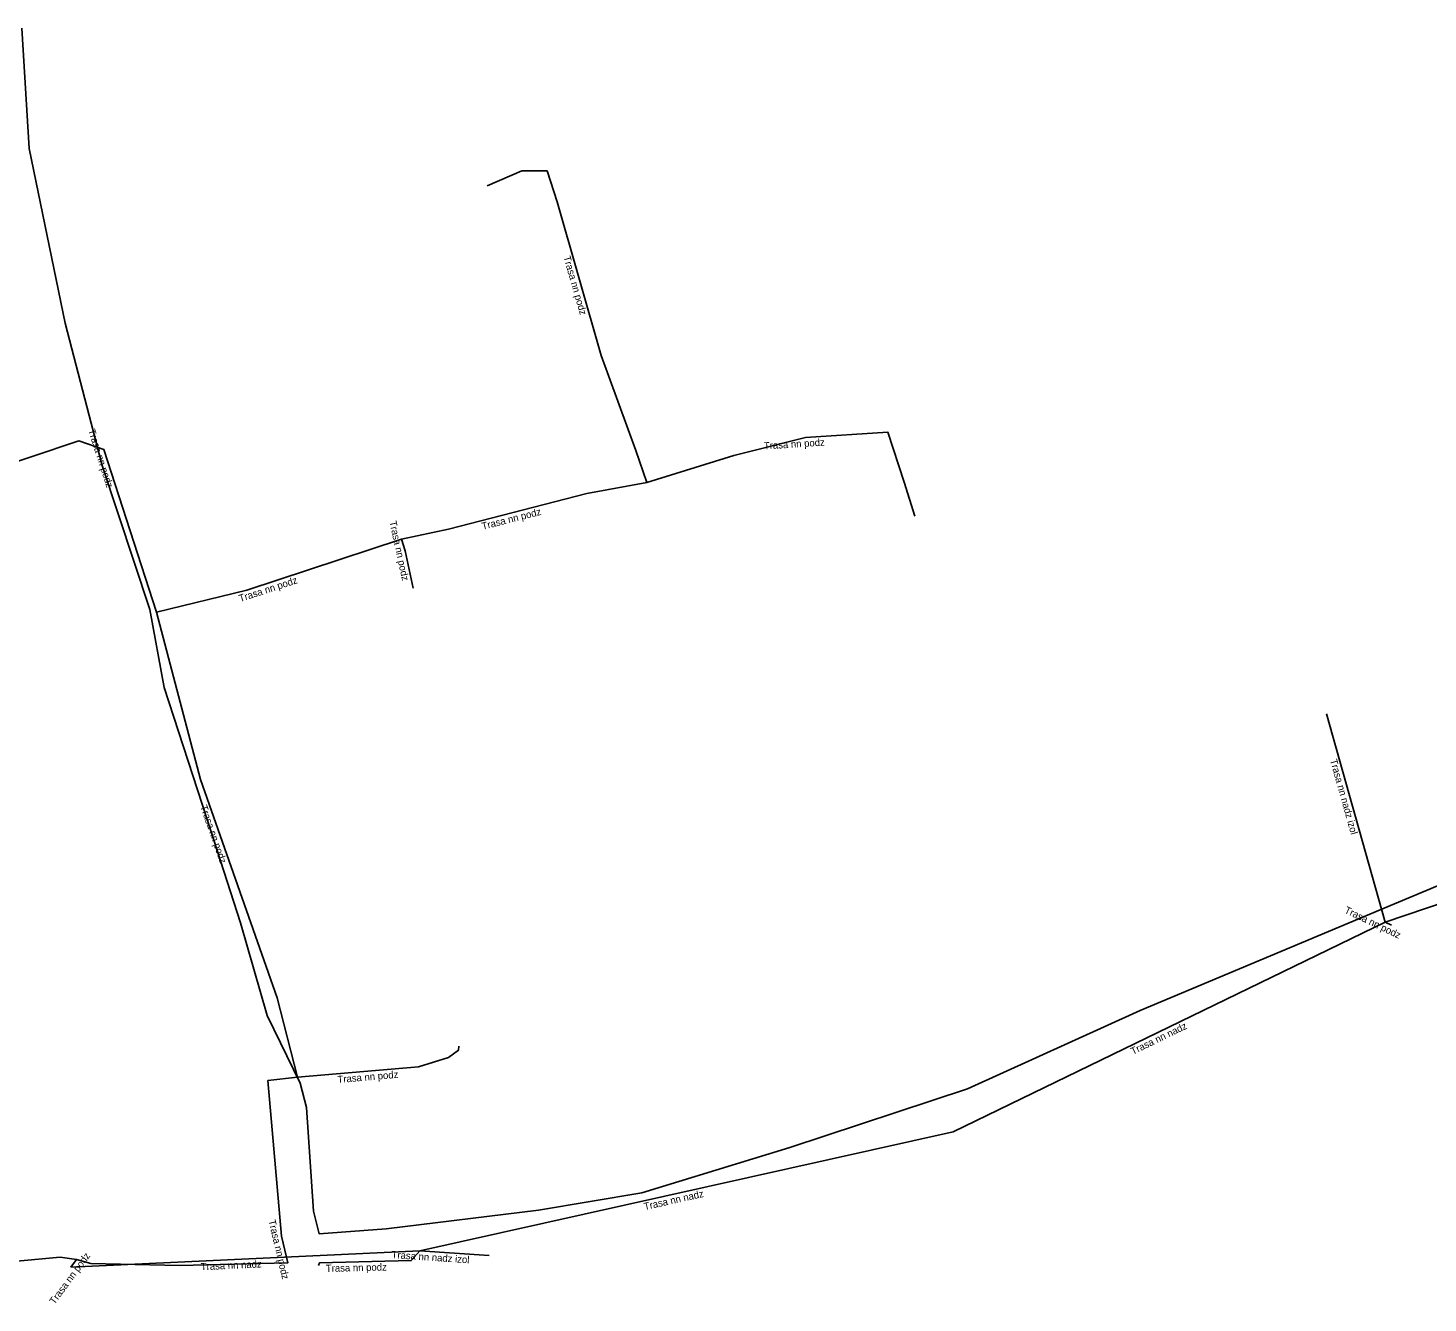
# Model space of a CAD drawing. Extents: x -682739 to -681564, y -1060091 to -1059590.
# Drawn here: x -682444.8 to -682346.7, y -1059848.4 to -1059759 of the extents above; entities that cross this region are included whole.
import ezdxf

# ---------------------------------------------------------------- set-up
doc = ezdxf.new("R2010")
doc.units = 0
for name, color, linetype in [('Popiskový text - Ostatní atributy Trasy', 7, 'Continuous'), ('Spojnice NN', 7, 'Continuous'), ('Spojnice VN', 7, 'Continuous')]:
    doc.layers.add(name, color=color, linetype=linetype)

msp = doc.modelspace()

# ---------------------------------------------------------------- linework, layer by layer
at = {"layer": 'Spojnice NN'}
for points in [[(-682401.45, -1059790.87), (-682402.21, -1059788.64), (-682404.64, -1059781.98), (-682407.73, -1059771.22), (-682408.44, -1059769.05), (-682410.2, -1059769.05), (-682412.64, -1059770.1)], [(-682435.82, -1059799.97), (-682439.5, -1059788.57), (-682441.27, -1059787.95), (-682447.96, -1059790.21)], [(-682401.45, -1059790.87), (-682395.35, -1059788.99), (-682390.33, -1059787.73), (-682384.55, -1059787.36), (-682383.4, -1059790.85), (-682382.67, -1059793.24)], [(-682418.65, -1059794.86), (-682415.35, -1059794.14), (-682405.66, -1059791.66), (-682401.45, -1059790.87)], [(-682435.82, -1059799.97), (-682429.48, -1059798.42), (-682418.65, -1059794.86)], [(-682418.65, -1059794.86), (-682418.39, -1059795.66), (-682417.82, -1059798.28)], [(-682425.93, -1059832.56), (-682427.37, -1059826.99), (-682432.74, -1059811.69), (-682435.82, -1059799.97)], [(-682353.799, -1059807.089), (-682349.7, -1059821.68)], [(-682349.7, -1059821.68), (-682328.04, -1059814.36)], [(-682379.97, -1059836.39), (-682349.7, -1059821.68)], [(-682349.7, -1059821.68), (-682349.249, -1059821.897)], [(-682425.93, -1059832.56), (-682417.45, -1059831.82), (-682415.36, -1059831.18), (-682414.66, -1059830.67), (-682414.62, -1059830.39)], [(-682441.43, -1059845.33), (-682440.43, -1059845.62), (-682434.2, -1059845.75), (-682426.61, -1059845.56), (-682427.05, -1059843.69), (-682428.01, -1059832.79), (-682425.93, -1059832.56)], [(-682417.36, -1059844.71), (-682379.97, -1059836.39)], [(-682441.82, -1059845.86), (-682417.36, -1059844.71)], [(-682417.36, -1059844.71), (-682417.96, -1059845.41), (-682424.39, -1059845.56), (-682424.46, -1059845.74)], [(-682417.36, -1059844.71), (-682412.496, -1059845.043)], [(-682462.45, -1059846.41), (-682454.44, -1059846.26), (-682442.57, -1059845.16), (-682441.43, -1059845.33)], [(-682441.43, -1059845.33), (-682441.82, -1059845.86)]]:
    msp.add_lwpolyline(points, dxfattribs=at)
at = {"layer": 'Spojnice VN'}
for points in [[(-682445.26, -1059759.03), (-682444.75, -1059767.47), (-682442.22, -1059779.72), (-682439.62, -1059789.68), (-682436.28, -1059799.78), (-682435.27, -1059805.25), (-682432.27, -1059814.5), (-682429.93, -1059821.74), (-682428.06, -1059828.23), (-682425.74, -1059832.96), (-682425.31, -1059834.68), (-682424.81, -1059841.93), (-682424.42, -1059843.52), (-682419.71, -1059843.18)], [(-682419.71, -1059843.18), (-682409.04, -1059841.86), (-682401.8, -1059840.66), (-682391.43, -1059837.47), (-682378.96, -1059833.37), (-682366.87, -1059827.88), (-682350.77, -1059821.14), (-682334.98, -1059814.51), (-682322.31, -1059809.45), (-682316.78, -1059807.47), (-682307.06, -1059804.21), (-682298.09, -1059802), (-682285.23, -1059800.25), (-682273.9, -1059799.1), (-682259.98, -1059797.91), (-682246.72, -1059796.96), (-682230, -1059795.42), (-682225.98, -1059795.71), (-682224.89, -1059801.14), (-682222.94, -1059818.12), (-682221.467, -1059834.279)]]:
    msp.add_lwpolyline(points, dxfattribs=at)

# ---------------------------------------------------------------- texts
at = {"layer": 'Popiskový text - Ostatní atributy Trasy'}
for s, rotation, p in [('Trasa nn podz', 286.02273, (-682407.3, -1059775.074)), ('Trasa nn podz', 287.89044, (-682440.618, -1059787.222)), ('Trasa nn podz', 3.66273, (-682393.227, -1059788.567)), ('Trasa nn podz', 14.35578, (-682412.954, -1059794.198)), ('Trasa nn podz', 282.27385, (-682419.498, -1059793.621)), ('Trasa nn podz', 18.19655, (-682429.952, -1059799.259)), ('Trasa nn nadz izol', 285.69147, (-682353.563, -1059810.334)), ('Trasa nn podz', 289.34007, (-682432.764, -1059813.583)), ('Trasa nn podz', 334.30533, (-682352.593, -1059821.01)), ('Trasa nn nadz', 25.91788, (-682367.382, -1059830.996)), ('Trasa nn podz', 4.98723, (-682423.108, -1059832.967)), ('Trasa nn nadz', 12.54503, (-682401.596, -1059841.868)), ('Trasa nn podz', 283.24052, (-682427.974, -1059842.6)), ('Trasa nn podz', 53.65254, (-682442.967, -1059848.515)), ('Trasa nn nadz izol', 356.08352, (-682419.352, -1059845.226)), ('Trasa nn nadz', 2.69181, (-682432.703, -1059846.083)), ('Trasa nn podz', 1.33636, (-682423.942, -1059846.199))]:
    msp.add_text(s, height=0.5, rotation=rotation, dxfattribs=at).set_placement(p)

doc.saveas('drawing.dxf')
